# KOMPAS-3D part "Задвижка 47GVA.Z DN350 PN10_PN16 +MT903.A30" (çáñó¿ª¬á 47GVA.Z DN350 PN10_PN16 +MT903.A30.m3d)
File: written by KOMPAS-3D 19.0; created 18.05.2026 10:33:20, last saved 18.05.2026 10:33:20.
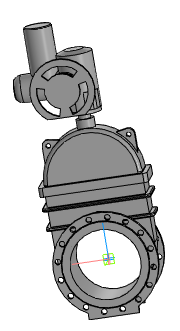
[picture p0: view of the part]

Document properties: Автор: Энергия; Полное имя файла: ..\Задвижка 47GVA.Z DN350_DN1200+MT903.A\Задвижка 47GVA.Z DN350 PN10_PN16 +MT903.A30.a3d

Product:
- Part/product: Задвижка 47GVA.Z DN350 PN10_PN16 +MT903.A30
    Масса: 579.823
  - Body: Электропривод МТ903.А30 без блока управления
      Масса: 163.268
  - Body: Задвижка 47GVA.Z DN350 PN10_PN16 без исполнит. мех.
      Масса: 416.555

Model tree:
1. Операция без истории:1
2. Операция без истории:2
